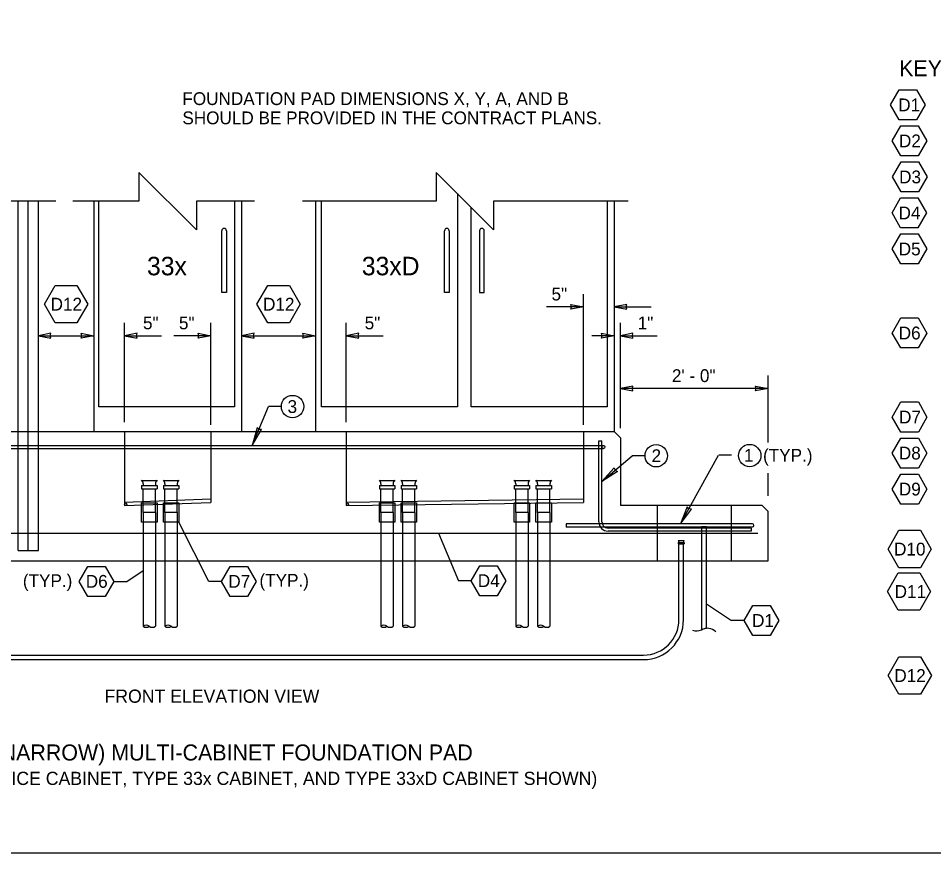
# Model space of a CAD drawing. Extents: x 99862 to 103151, y 100000 to 117076.
# Drawn here: x 100575 to 101719, y 112000 to 113042 of the extents above; entities that cross this region are included whole.
import ezdxf

# ---------------------------------------------------------------- set-up
doc = ezdxf.new("R2010")
doc.units = 0
for name, color, linetype in [('Default', 7, 'Continuous'), ('Level 1', 7, 'Continuous'), ('Level 11', 7, 'Continuous'), ('Level 15', 7, 'Continuous'), ('Level 20', 7, 'Continuous'), ('Level 40', 7, 'Continuous'), ('Level 6', 7, 'Continuous')]:
    doc.layers.add(name, color=color, linetype=linetype)

msp = doc.modelspace()

# ---------------------------------------------------------------- linework, layer by layer
at = {"layer": 'Default'}
for p, q in [((100436.9, 112508.3), (101306.5, 112508.3)), ((100436.9, 112504.5), (101306.5, 112504.5)), ((101300.7, 112412.8), (101300.7, 112514.1)), ((101300.7, 112514.1), (101304.5, 112514.1)), ((101304.5, 112412.8), (101304.5, 112514.1)), ((101492.5, 112410.3), (101260, 112410.3)), ((101260, 112410.3), (101260, 112406.4)), ((101492.5, 112406.4), (101260, 112406.4)), ((101491.1, 112405.1), (101312.2, 112405.1)), ((101491.1, 112401.2), (101312.2, 112401.2)), ((101491.1, 112405.1), (101491.1, 112401.2))]:
    msp.add_line(p, q, dxfattribs=at)
for centre, radius in [((101306.5, 112506.4), 1.92), ((100709.6, 112434.8), 1.44), ((100986.7, 112434.8), 1.44)]:
    msp.add_circle(centre, radius, dxfattribs=at)
for centre, radius, start, end in [((101312.2, 112412.8), 11.5, 180, 270), ((101312.2, 112412.8), 7.7, 180, 270), ((101492.5, 112408.4), 1.92, 270, 90)]:
    msp.add_arc(centre, radius, start, end, dxfattribs=at)
at = {"layer": 'Level 1'}
for p, q in [((100946.7, 112813.6), (100946.7, 112525.6)), ((101319.9, 112813.6), (101319.9, 112525.6)), ((101107.9, 112772.7), (101107.9, 112776.5)), ((101107.9, 112699.3), (101107.9, 112772.7)), ((101113.7, 112776.5), (101113.7, 112772.7)), ((101113.7, 112772.7), (101113.7, 112699.3)), ((101151.7, 112776.5), (101151.7, 112772.7)), ((101151.7, 112772.7), (101151.7, 112699.3)), ((101157.5, 112772.7), (101157.5, 112776.5)), ((101157.5, 112699.3), (101157.5, 112772.7)), ((101113.7, 112699.3), (101107.9, 112699.3)), ((101151.7, 112699.3), (101157.5, 112699.3)), ((100729.5, 112464.7), (100748.7, 112464.7)), ((100729.5, 112458.4), (100729.5, 112453.9)), ((100729.5, 112458.4), (100748.7, 112458.4)), ((100731.4, 112460.2), (100731.4, 112458.4)), ((100746.8, 112460.2), (100746.8, 112458.4)), ((100748.7, 112458.4), (100748.7, 112453.9)), ((100756.7, 112464.7), (100775.9, 112464.7)), ((100756.7, 112458.4), (100756.7, 112453.9)), ((100756.7, 112458.4), (100775.9, 112458.4)), ((100758.6, 112460.2), (100758.6, 112458.4)), ((100774, 112460.2), (100774, 112458.4)), ((100775.9, 112458.4), (100775.9, 112453.9)), ((101026.5, 112464.7), (101045.7, 112464.7)), ((101026.5, 112458.4), (101026.5, 112453.9)), ((101026.5, 112458.4), (101045.7, 112458.4)), ((101028.4, 112460.2), (101028.4, 112458.4)), ((101043.8, 112460.2), (101043.8, 112458.4)), ((101045.7, 112458.4), (101045.7, 112453.9)), ((101053.7, 112464.7), (101072.9, 112464.7)), ((101053.7, 112458.4), (101053.7, 112453.9)), ((101053.7, 112458.4), (101072.9, 112458.4)), ((101055.6, 112460.2), (101055.6, 112458.4)), ((101071, 112460.2), (101071, 112458.4)), ((101072.9, 112458.4), (101072.9, 112453.9)), ((101195, 112464.7), (101214.3, 112464.7)), ((101195, 112458.4), (101195, 112453.9)), ((101195, 112458.4), (101214.3, 112458.4)), ((101196.9, 112460.2), (101196.9, 112458.4)), ((101212.3, 112460.2), (101212.3, 112458.4)), ((101214.3, 112458.4), (101214.3, 112453.9)), ((101222.2, 112464.7), (101241.5, 112464.7)), ((101222.2, 112458.4), (101222.2, 112453.9)), ((101222.2, 112458.4), (101241.5, 112458.4)), ((101224.2, 112460.2), (101224.2, 112458.4)), ((101239.5, 112460.2), (101239.5, 112458.4)), ((101241.5, 112458.4), (101241.5, 112453.9)), ((100729.5, 112453.9), (100748.7, 112453.9)), ((100731.4, 112424.5), (100731.4, 112453.9)), ((100746.8, 112424.5), (100746.8, 112453.9)), ((100756.7, 112453.9), (100775.9, 112453.9)), ((100758.6, 112424.5), (100758.6, 112453.9)), ((100774, 112424.5), (100774, 112453.9)), ((101026.5, 112453.9), (101045.7, 112453.9)), ((101028.4, 112424.5), (101028.4, 112453.9)), ((101043.8, 112424.5), (101043.8, 112453.9)), ((101053.7, 112453.9), (101072.9, 112453.9)), ((101055.6, 112424.5), (101055.6, 112453.9)), ((101071, 112424.5), (101071, 112453.9)), ((101195, 112453.9), (101214.3, 112453.9)), ((101196.9, 112424.5), (101196.9, 112453.9)), ((101212.3, 112424.5), (101212.3, 112453.9)), ((101222.2, 112453.9), (101241.5, 112453.9)), ((101224.2, 112424.5), (101224.2, 112453.9)), ((101239.5, 112424.5), (101239.5, 112453.9)), ((100746.8, 112424.5), (100731.4, 112424.5)), ((100731.4, 112424.5), (100731.4, 112282.4)), ((100746.8, 112424.5), (100746.8, 112282.4)), ((100774, 112424.5), (100758.6, 112424.5)), ((100758.6, 112424.5), (100758.6, 112282.4)), ((100774, 112424.5), (100774, 112282.4)), ((101043.8, 112424.5), (101028.4, 112424.5)), ((101028.4, 112424.5), (101028.4, 112282.4)), ((101043.8, 112424.5), (101043.8, 112282.4)), ((101071, 112424.5), (101055.6, 112424.5)), ((101055.6, 112424.5), (101055.6, 112282.4)), ((101071, 112424.5), (101071, 112282.4)), ((101212.3, 112424.5), (101196.9, 112424.5)), ((101196.9, 112424.5), (101196.9, 112282.4)), ((101212.3, 112424.5), (101212.3, 112282.4)), ((101239.5, 112424.5), (101224.2, 112424.5)), ((101224.2, 112424.5), (101224.2, 112282.4)), ((101239.5, 112424.5), (101239.5, 112282.4)), ((101400, 112389.5), (101407.2, 112389.5)), ((101400, 112387.1), (101400, 112385.4)), ((101400, 112387.1), (101407.2, 112387.1)), ((101400, 112385.4), (101407.2, 112385.4)), ((101400.7, 112387.8), (101400.7, 112387.1)), ((101400.7, 112289.1), (101400.7, 112385.4)), ((101406.5, 112387.8), (101406.5, 112387.1)), ((101406.5, 112289), (101406.5, 112385.4)), ((101407.2, 112387.1), (101407.2, 112385.4)), ((100272.7, 112246.4), (101356.5, 112246.4)), ((100272.7, 112240.7), (101356.5, 112240.7))]:
    msp.add_line(p, q, dxfattribs=at)
for points in [[(99862, 111999.5), (103151, 111999.5), (103151, 114075.5), (99862, 114075.5)], [(100748.7, 112412.6), (100729.5, 112412.6), (100729.5, 112436.5), (100748.7, 112436.5)], [(100775.9, 112412.6), (100756.7, 112412.6), (100756.7, 112436.5), (100775.9, 112436.5)], [(101045.7, 112412.6), (101026.5, 112412.6), (101026.5, 112436.5), (101045.7, 112436.5)], [(101072.9, 112412.6), (101053.7, 112412.6), (101053.7, 112436.5), (101072.9, 112436.5)], [(101214.3, 112412.6), (101195, 112412.6), (101195, 112436.5), (101214.3, 112436.5)], [(101241.5, 112412.6), (101222.2, 112412.6), (101222.2, 112436.5), (101241.5, 112436.5)], [(101429, 112406.5), (101429, 112278), (101431.2, 112279.1), (101433.2, 112279.6), (101435.3, 112280), (101435.3, 112406.5)]]:
    msp.add_lwpolyline(points, close=True, dxfattribs=at)
for points in [[(101124, 112822.9), (101124, 112556.5), (100954.2, 112556.5), (100954.2, 112813.6)], [(101311.2, 112813.6), (101311.2, 112556.5), (101141.4, 112556.5), (101141.4, 112805.5)]]:
    msp.add_lwpolyline(points, dxfattribs=at)
for centre, radius, start, end in [((101110.8, 112776.5), 2.9, 0, 180), ((101154.6, 112776.5), 2.9, 0, 180), ((100725.1, 112460.2), 6.32, 0, 45.9402), ((100753.1, 112460.2), 6.32, 134.0598, 180), ((100752.3, 112460.2), 6.32, 0, 45.9402), ((100780.3, 112460.2), 6.32, 134.0598, 180), ((101022.1, 112460.2), 6.32, 0, 45.9402), ((101050.1, 112460.2), 6.32, 134.0598, 180), ((101049.3, 112460.2), 6.32, 0, 45.9402), ((101077.3, 112460.2), 6.32, 134.0598, 180), ((101190.6, 112460.2), 6.32, 0, 45.9402), ((101218.6, 112460.2), 6.32, 134.0598, 180), ((101217.8, 112460.2), 6.32, 0, 45.9402), ((101245.9, 112460.2), 6.32, 134.0598, 180), ((101398.3, 112387.8), 2.37, 0, 45.9402), ((101408.8, 112387.8), 2.37, 134.0598, 180), ((101356.5, 112290.7), 44.3, 270, 0), ((101356.5, 112290.7), 50, 270, 0), ((100735.2, 112277.7), 6.09, 50.8329, 129.1671), ((100735.2, 112287.2), 6.09, 230.8329, 309.1671), ((100742.9, 112287.2), 6.09, 230.8329, 309.1671), ((100762.5, 112277.7), 6.09, 50.8329, 129.1671), ((100762.5, 112287.2), 6.09, 230.8329, 309.1671), ((100770.1, 112287.2), 6.09, 230.8329, 309.1671), ((101032.2, 112277.7), 6.09, 50.8329, 129.1671), ((101032.2, 112287.2), 6.09, 230.8329, 309.1671), ((101039.9, 112287.2), 6.09, 230.8329, 309.1671), ((101059.4, 112277.7), 6.09, 50.8329, 129.1671), ((101059.4, 112287.2), 6.09, 230.8329, 309.1671), ((101067.1, 112287.2), 6.09, 230.8329, 309.1671), ((101200.8, 112277.7), 6.09, 50.8329, 129.1671), ((101200.8, 112287.2), 6.09, 230.8329, 309.1671), ((101208.5, 112287.2), 6.09, 230.8329, 309.1671), ((101228, 112277.7), 6.09, 50.8329, 129.1671), ((101228, 112287.2), 6.09, 230.8329, 309.1671), ((101235.7, 112287.2), 6.09, 230.8329, 309.1671), ((101422.7, 112291.1), 14.6, 250.7571, 295.3506), ((101436.3, 112265.8), 14.1, 42.3778, 121.1813)]:
    msp.add_arc(centre, radius, start, end, dxfattribs=at)
at = {"layer": 'Level 11'}
for p, q in [((100708.2, 112525.6), (100708.2, 112433.3)), ((100815.9, 112525.6), (100815.9, 112437.1)), ((100985.2, 112525.6), (100985.2, 112433.3)), ((101281.5, 112525.6), (101281.5, 112437.1)), ((100815.9, 112441), (100708.2, 112437.1)), ((100708.2, 112433.3), (100815.9, 112437.1)), ((101281.5, 112441), (100985.2, 112437.1)), ((100985.2, 112433.3), (101281.5, 112437.1)), ((101373.8, 112433.3), (101373.8, 112364)), ((101466.1, 112433.3), (101466.1, 112364))]:
    msp.add_line(p, q, dxfattribs=at)
for points in [[(100423.5, 112525.6), (101319.9, 112525.6)], [(101319.9, 112525.6), (101327.6, 112517.9), (101327.6, 112433.3)], [(101512.3, 112364), (101512.3, 112425.6), (101504.6, 112433.3), (101327.6, 112433.3)], [(100138.8, 112364), (101512.3, 112364)]]:
    msp.add_lwpolyline(points, dxfattribs=at)
at = {"layer": 'Level 15'}
for p, q in [((101281.4, 112534.1), (101281.4, 112697.5)), ((101281.4, 112681.5), (101235.3, 112681.5)), ((101319.9, 112681.5), (101366.1, 112681.5)), ((100708.2, 112537.6), (100708.2, 112661.4)), ((100815.9, 112534.1), (100815.9, 112661.4)), ((100985.2, 112537.6), (100985.2, 112661.4)), ((101327.6, 112529.9), (101327.6, 112661.4)), ((100600.5, 112645.4), (100669.7, 112645.4)), ((100708.2, 112645.4), (100754.4, 112645.4)), ((100815.9, 112645.4), (100769.7, 112645.4)), ((100854.4, 112645.4), (100946.7, 112645.4)), ((100985.2, 112645.4), (101031.4, 112645.4)), ((101319.9, 112645.4), (101291.9, 112645.4)), ((101327.6, 112645.4), (101373.8, 112645.4)), ((101512.3, 112511.9), (101512.3, 112595.5)), ((101512.3, 112579.5), (101327.6, 112579.5)), ((100867.8, 112508.3), (100888.1, 112556.9)), ((100904.1, 112556.9), (100888.1, 112556.9)), ((101304.5, 112463.4), (101342.4, 112495.5)), ((101358.4, 112495.5), (101342.4, 112495.5)), ((101402.7, 112410.3), (101450.4, 112496)), ((101466.5, 112496), (101450.5, 112496)), ((101512.3, 112445.3), (101512.3, 112473.8)), ((100813.4, 112338.5), (100775.9, 112412.6)), ((101100.6, 112398.7), (101125.3, 112339.3)), ((100710.8, 112338.5), (100731.4, 112351.9)), ((100694.8, 112338.5), (100710.8, 112338.5)), ((100829.4, 112338.5), (100813.4, 112338.5)), ((101141.3, 112339.3), (101125.3, 112339.3)), ((101435.3, 112310.5), (101466.4, 112289.6)), ((101482.4, 112289.6), (101466.4, 112289.6))]:
    msp.add_line(p, q, dxfattribs=at)
for points in [[(100622.2, 112813.6), (100544.5, 112813.6), (100544.5, 112777.7), (100472.7, 112849.5), (100472.7, 112813.6), (100383.4, 112813.6)], [(100870.5, 112813.6), (100797.9, 112813.6), (100797.9, 112777.7), (100726.1, 112849.5), (100726.1, 112813.6), (100643.6, 112813.6)], [(101337.4, 112813.6), (101169.2, 112813.6), (101169.2, 112777.7), (101097.4, 112849.5), (101097.4, 112813.6), (100930.4, 112813.6)]]:
    msp.add_lwpolyline(points, dxfattribs=at)
for points in [[(101281.4, 112681.5), (101265.7, 112678.5), (101266.4, 112681.5), (101265.7, 112684.6)], [(101319.9, 112681.5), (101335.7, 112678.5), (101334.9, 112681.5), (101335.7, 112684.6)], [(100600.5, 112645.4), (100616.2, 112642.3), (100615.4, 112645.4), (100616.2, 112648.5)], [(100669.7, 112645.4), (100654, 112642.3), (100654.7, 112645.4), (100654, 112648.5)], [(100708.2, 112645.4), (100723.9, 112642.3), (100723.2, 112645.4), (100723.9, 112648.5)], [(100815.9, 112645.4), (100800.2, 112642.3), (100800.9, 112645.4), (100800.2, 112648.5)], [(100854.4, 112645.4), (100870.1, 112642.3), (100869.4, 112645.4), (100870.1, 112648.5)], [(100946.7, 112645.4), (100931, 112642.3), (100931.7, 112645.4), (100931, 112648.5)], [(100985.2, 112645.4), (101000.9, 112642.3), (101000.2, 112645.4), (101000.9, 112648.5)], [(101319.9, 112645.4), (101304.2, 112642.3), (101304.9, 112645.4), (101304.2, 112648.5)], [(101327.6, 112645.4), (101343.4, 112642.3), (101342.6, 112645.4), (101343.4, 112648.5)], [(101327.6, 112579.5), (101343.4, 112576.4), (101342.6, 112579.5), (101343.4, 112582.5)], [(101512.3, 112579.5), (101496.6, 112576.4), (101497.3, 112579.5), (101496.6, 112582.5)], [(100867.8, 112508.3), (100879.3, 112528.2), (100876.2, 112528.4), (100873.8, 112530.5)], [(101304.5, 112463.4), (101320, 112480.5), (101321.2, 112477.5), (101323.9, 112475.9)], [(101402.7, 112410.3), (101416.4, 112428.8), (101413.3, 112429.3), (101411.2, 112431.7)]]:
    msp.add_lwpolyline(points, close=True, dxfattribs=at)
at = {"layer": 'Level 20'}
for points in [[(101665.1, 112933.8), (101675.9, 112952.6), (101697.6, 112952.6), (101708.4, 112933.8), (101697.6, 112915.1), (101675.9, 112915.1), (101665.1, 112933.8)], [(101667.3, 112888.8), (101678.2, 112907.6), (101699.8, 112907.6), (101710.6, 112888.8), (101699.8, 112870.1), (101678.2, 112870.1), (101667.3, 112888.8)], [(101667.7, 112843.8), (101678.5, 112862.6), (101700.2, 112862.6), (101711, 112843.8), (101700.2, 112825.1), (101678.5, 112825.1), (101667.7, 112843.8)], [(101667, 112798.8), (101677.8, 112817.6), (101699.4, 112817.6), (101710.3, 112798.8), (101699.4, 112780.1), (101677.8, 112780.1), (101667, 112798.8)], [(101667.2, 112753.8), (101678, 112772.6), (101699.6, 112772.6), (101710.5, 112753.8), (101699.6, 112735.1), (101678, 112735.1), (101667.2, 112753.8)], [(100608, 112684.8), (100621.5, 112708.3), (100648.6, 112708.3), (100662.1, 112684.8), (100648.6, 112661.4), (100621.5, 112661.4), (100608, 112684.8)], [(100873.5, 112684.8), (100887, 112708.3), (100914.1, 112708.3), (100927.6, 112684.8), (100914.1, 112661.4), (100887, 112661.4), (100873.5, 112684.8)], [(101667.2, 112648.8), (101678, 112667.6), (101699.6, 112667.6), (101710.5, 112648.8), (101699.6, 112630.1), (101678, 112630.1), (101667.2, 112648.8)], [(101667.4, 112543.8), (101678.2, 112562.6), (101699.9, 112562.6), (101710.7, 112543.8), (101699.9, 112525.1), (101678.2, 112525.1), (101667.4, 112543.8)], [(101667.4, 112498.8), (101678.2, 112517.6), (101699.9, 112517.6), (101710.7, 112498.8), (101699.9, 112480.1), (101678.2, 112480.1), (101667.4, 112498.8)], [(101667.4, 112453.8), (101678.2, 112472.6), (101699.9, 112472.6), (101710.7, 112453.8), (101699.9, 112435.1), (101678.2, 112435.1), (101667.4, 112453.8)], [(101662, 112378.8), (101675.5, 112402.3), (101702.6, 112402.3), (101716.1, 112378.8), (101702.6, 112355.4), (101675.5, 112355.4), (101662, 112378.8)], [(100651.5, 112338.5), (100662.3, 112357.2), (100684, 112357.2), (100694.8, 112338.5), (100684, 112319.7), (100662.3, 112319.7), (100651.5, 112338.5)], [(100829.4, 112338.5), (100840.2, 112357.2), (100861.9, 112357.2), (100872.7, 112338.5), (100861.9, 112319.7), (100840.2, 112319.7), (100829.4, 112338.5)], [(101141.3, 112339.3), (101152.1, 112358.1), (101173.8, 112358.1), (101184.6, 112339.3), (101173.8, 112320.6), (101152.1, 112320.6), (101141.3, 112339.3)], [(101661.2, 112325.8), (101674.7, 112349.3), (101701.8, 112349.3), (101715.3, 112325.8), (101701.8, 112302.4), (101674.7, 112302.4), (101661.2, 112325.8)], [(101482.4, 112289.6), (101493.2, 112308.4), (101514.9, 112308.4), (101525.7, 112289.6), (101514.9, 112270.9), (101493.2, 112270.9), (101482.4, 112289.6)], [(101662.1, 112220.8), (101675.7, 112244.3), (101702.7, 112244.3), (101716.2, 112220.8), (101702.7, 112197.4), (101675.7, 112197.4), (101662.1, 112220.8)]]:
    msp.add_lwpolyline(points, dxfattribs=at)
for centre in [(100918.1, 112556.9), (101372.4, 112495.5), (101489.2, 112495.6)]:
    msp.add_circle(centre, 14, dxfattribs=at)
at = {"layer": 'Level 40'}
for p, q in [((100575.4, 112525.6), (100575.4, 112813.6)), ((100587.9, 112525.6), (100587.9, 112813.6)), ((100600.5, 112525.6), (100600.5, 112813.6)), ((100575.4, 112377), (100575.4, 112525.6)), ((100587.9, 112377), (100587.9, 112525.6)), ((100600.5, 112377), (100600.5, 112525.6)), ((100151.6, 112398.7), (101499.5, 112398.7)), ((100575.4, 112377), (100587.9, 112377)), ((100587.9, 112377), (100600.5, 112377))]:
    msp.add_line(p, q, dxfattribs=at)
at = {"layer": 'Level 6'}
for p, q in [((100669.7, 112813.6), (100669.7, 112525.6)), ((100854.4, 112813.6), (100854.4, 112525.6)), ((100829.6, 112772.7), (100829.6, 112776.5)), ((100829.6, 112699.3), (100829.6, 112772.7)), ((100835.4, 112776.5), (100835.4, 112772.7)), ((100835.4, 112772.7), (100835.4, 112699.3)), ((100835.4, 112699.3), (100829.6, 112699.3))]:
    msp.add_line(p, q, dxfattribs=at)
msp.add_lwpolyline([(100845.7, 112813.6), (100845.7, 112556.5), (100675.9, 112556.5), (100675.9, 112813.6)], dxfattribs=at)
msp.add_arc((100832.5, 112776.5), 2.9, 0, 180, dxfattribs=at)

# ---------------------------------------------------------------- texts
at = {"layer": 'Level 1'}
msp.add_text('33xD', height=23.09, dxfattribs=at).set_placement((101004.6, 112720.9))
at = {"layer": 'Level 20'}
for s, height, p in [('KEY NOTES - SHEET 5 OF 6', 20, (101675.9, 112969.6)), ('FOUNDATION PAD DIMENSIONS X, Y, A, AND B', 16, (100780.4, 112933.6)), ('D1', 16, (101674.8, 112925.8)), ('SHOULD BE PROVIDED IN THE CONTRACT PLANS.', 16, (100780.4, 112909.6)), ('D2', 16, (101675.7, 112880.8)), ('D3', 16, (101675.9, 112835.8)), ('D4', 16, (101675.2, 112790.8)), ('D5', 16, (101675.4, 112745.8)), ('5"', 16, (101241.6, 112689.5)), ('D12', 16, (100615.8, 112676.8)), ('D12', 16, (100881.2, 112676.8)), ('5"', 16, (100731.2, 112653.4)), ('5"', 16, (100776.1, 112653.4)), ('5"', 16, (101008.2, 112653.4)), ('1"', 16, (101349.3, 112653.4)), ('D6', 16, (101675.4, 112640.8)), ('2\' - 0"', 16, (101392, 112587.5)), ('3', 16, (100911.8, 112548.9)), ('D7', 16, (101675.8, 112535.8)), ('2', 16, (101366.6, 112487.5)), ('1  (TYP.)', 16, (101482.1, 112488)), ('D8', 16, (101675.6, 112490.8)), ('D9', 16, (101675.6, 112445.8)), ('D10', 16, (101669.6, 112370.8)), ('(TYP.)', 16, (100581.1, 112331.3)), ('D6', 16, (100659.7, 112330.5)), ('D7', 16, (100837.8, 112330.5)), ('(TYP.)', 16, (100876.7, 112331.8)), ('D4', 16, (101149.5, 112331.3)), ('D11', 16, (101670.3, 112317.8)), ('D1', 16, (101492.2, 112281.6)), ('D12', 16, (101669.9, 112212.8)), ('FRONT ELEVATION VIEW', 16.5, (100683.1, 112186.8)), ('TYPE A (NARROW) MULTI-CABINET FOUNDATION PAD', 20, (100441.9, 112114.7)), ('(TYPE B MODIFIED SERVICE CABINET, TYPE 33x CABINET, AND TYPE 33xD CABINET SHOWN)', 16.5, (100300.8, 112084.1))]:
    msp.add_text(s, height=height, dxfattribs=at).set_placement(p)
at = {"layer": 'Level 6'}
msp.add_text('33x', height=23.09, dxfattribs=at).set_placement((100736.2, 112720.9))

doc.saveas('drawing.dxf')
